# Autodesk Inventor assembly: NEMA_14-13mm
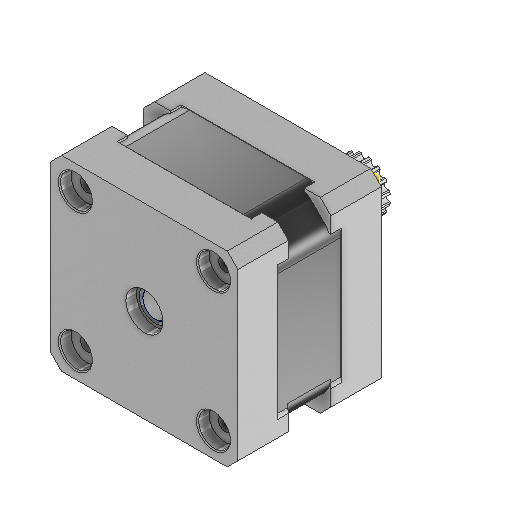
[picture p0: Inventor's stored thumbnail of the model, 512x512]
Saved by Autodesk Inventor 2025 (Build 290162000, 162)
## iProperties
Created: 2019-11
Part Number: NEMA_14-13mm
Material: Générique
Document SubType Name: Assembly
Designer: thoma
Author: thoma
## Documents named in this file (4)
- C:\Users\Ryzen5700u\Desktop\robot nema 14 v2\Workgroups\NotInProject\NEMA_14-13mm.iam
- C:\Users\Ryzen5700u\Desktop\robot nema 14 v2\Workgroups\NotInProject\NEMA_14HM11-0404S_BODY.ipt
- C:\Users\Ryzen5700u\Desktop\robot nema 14 v2\Workgroups\NotInProject\GT2 16 Teeth Free Pulley.ipt
- C:\Users\Ryzen5700u\Desktop\robot nema 14 v2\Workgroups\NotInProject\NEMA_14HM11-0404S_SHAFT13.ipt
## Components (3 placed, 3 different names)
1. NEMA_14HM11-0404S:1 — Affleurement:2, Placage:2, Placage:3, Affleurement:3
2. NEMA_14HM11-0404S_SHAFT13:1 — Affleurement:3, Rotazionale:1
3. GT2 16 Teeth Free Pulley:1 — Rotazionale:1
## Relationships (5: Flush 2, Mate 2, RevoluteJoint 1)
- Affleurement:2 [Flush]: NEMA_14HM11-0404S:1
- Placage:2 [Mate]: NEMA_14HM11-0404S:1
- Placage:3 [Mate]: NEMA_14HM11-0404S:1
- Affleurement:3 [Flush]: NEMA_14HM11-0404S:1 ↔ NEMA_14HM11-0404S_SHAFT13:1
- Rotazionale:1 [RevoluteJoint]: NEMA_14HM11-0404S_SHAFT13:1 ↔ GT2 16 Teeth Free Pulley:1
